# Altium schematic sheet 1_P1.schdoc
size 307 x 218 mm; Symbol: Drawing-Symbol_A4; Device: Drawing-Symbol_A4; @Project Name: elrsTransmitter; @Page Count: 1; @Update Date: 2026-03-08; @Create Date: 2026-03-08; @Schematic Name: Schematic2; @Page No: 1; @Page Name: P1; Company: EasyEDA.com; Version: V1.0; Page Size: A4; @Create Time: 09:29:20; @Update Time: 11:20:45; Width: 1170; Height: 825; Region Start: 1; X Region Count: 6; Y Region Count: 4; Blade Width: 10; Title Block Position: 3; @Board Name: PCB2
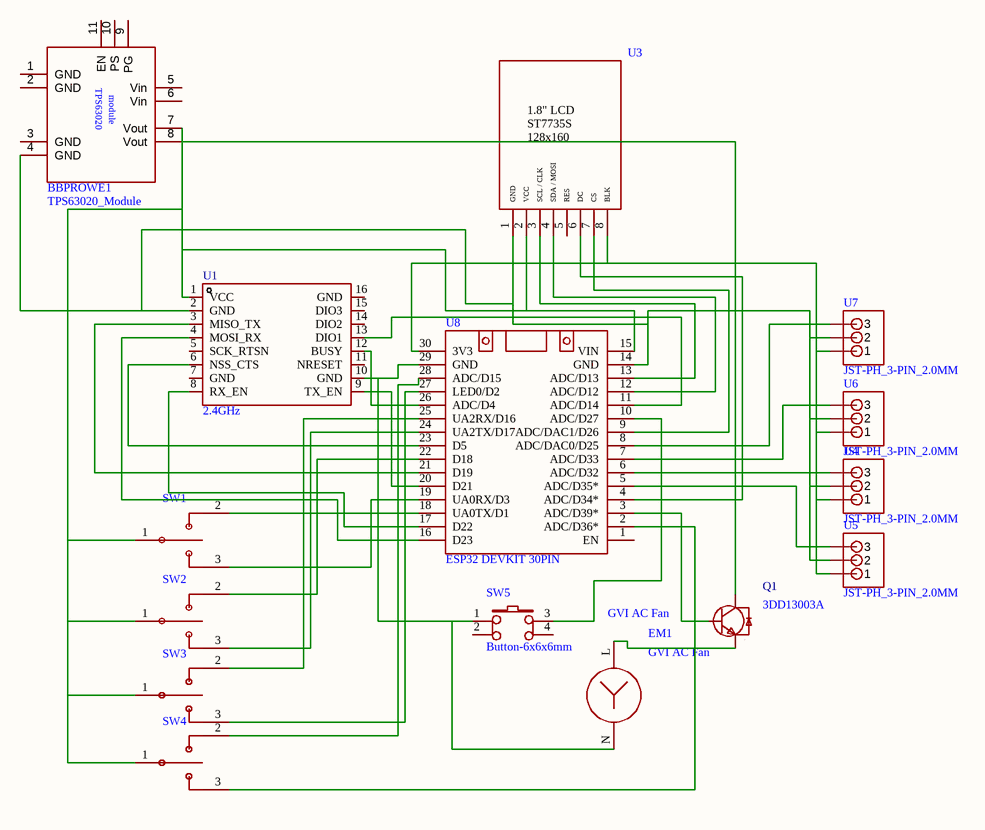
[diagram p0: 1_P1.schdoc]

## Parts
BBPROWE1  TPS63020_Module  [TPS63020_MODULE_PCB]
EM1  GVI AC Fan  [CONN-TH_2P-P2.54-V]
Q1  3DD13003A  [TO-92-3_L4.8-W3.7-P1.27-L]
SW1  (no value)  [3_Pin_Toggle_Switch_Footprint]
SW2  (no value)  [3_Pin_Toggle_Switch_Footprint]
SW3  (no value)  [3_Pin_Toggle_Switch_Footprint]
SW4  (no value)  [3_Pin_Toggle_Switch_Footprint]
SW5  Button-6x6x6mm  [SW-TH_4PIN-L6.00-W6.00]
U1  2.4GHz  [WIRELM-SMD_E28-2G4M27SX]
U3  (no value)  [WeAct 1.8 inch TFT ST7735S]
U4  JST-PH_3-PIN_2.0MM  [JST PH 3-PIN 2.0MM TOP ENTRY]
U5  JST-PH_3-PIN_2.0MM  [JST PH 3-PIN 2.0MM TOP ENTRY]
U6  JST-PH_3-PIN_2.0MM  [JST PH 3-PIN 2.0MM TOP ENTRY]
U7  JST-PH_3-PIN_2.0MM  [JST PH 3-PIN 2.0MM TOP ENTRY]
U8  ESP32 DEVKIT 30PIN  [ESP32 DEVKIT 30P]

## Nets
NetBBPROWE1_4: BBPROWE1.4(GND) U1.2(GND) U3.1(GND) U4.2 U5.2 U6.2 U7.2 U8.14(GND)
NetBBPROWE1_7: BBPROWE1.7(Vout) BBPROWE1.8(Vout) Q1.2(C) SW1.1 SW2.1 SW3.1 SW4.1 U1.1(VCC) U3.2(VCC) U8.15(VIN)
NetEM1_L: EM1.L Q1.1(E)
NetEM1_N: EM1.N SW5.1 U1.10(GND) U8.29(GND)
NetQ1_3: Q1.3(B) U8.3(ADC/D39*)
NetSW1_2: SW1.2 U8.18(UA0TX/D1)
NetSW1_3: SW1.3 U8.19(UA0RX/D3)
NetSW2_2: SW2.2 U8.22(D18)
NetSW2_3: SW2.3 U8.24(UA2TX/D17)
NetSW3_2: SW3.2 U8.25(UA2RX/D16)
NetSW3_3: SW3.3 U8.27(LED0/D2)
NetSW4_2: SW4.2 U8.28(ADC/D15)
NetSW4_3: SW4.3 U8.2(ADC/D36*)
NetSW5_3: SW5.3 U8.10(ADC/D27)
NetU1_3: U1.3(MISO_TX) U8.21(D19)
NetU1_4: U1.4(MOSI_RX) U8.16(D23)
NetU1_6: U1.6(NSS_CTS) U8.23(D5)
NetU1_8: U1.8(RX_EN) U8.17(D22)
NetU1_9: U1.9(TX_EN) U8.20(D21)
NetU1_12: U1.12(BUSY) U8.26(ADC/D4)
NetU1_13: U1.13(DIO1) U8.11(ADC/D14)
NetU3_3: U3.3(SCL_/_CLK) U8.13(ADC/D13)
NetU3_4: U3.4(SDA_/_MOSI) U8.12(ADC/D12)
NetU3_6: U3.6(DC) U8.4(ADC/D34*)
NetU3_7: U3.7(CS) U8.9(ADC/DAC1/D26)
NetU3_8: U3.8(BLK) U4.1 U5.1 U6.1 U7.1 U8.30(3V3)
NetU4_3: U4.3 U8.6(ADC/D32)
NetU5_3: U5.3 U8.5(ADC/D35*)
NetU6_3: U6.3 U8.7(ADC/D33)
NetU7_3: U7.3 U8.8(ADC/DAC0/D25)

Not connected (* = marked no-connect by the designer): BBPROWE1 1(GND) 2(GND) 3(GND) 5(Vin) 6(Vin) 9(PG) 10(PS) 11(EN); SW5 2 4; U1 5(SCK_RTSN) 7(GND) 11(NRESET) 14(DIO2) 15(DIO3) 16(GND); U3 5(RES); U8 1(EN)

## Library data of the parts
BBPROWE1 = TPS63020_Module: Add into BOM: yes
EM1 = GVI AC Fan: Add into BOM: yes
Q1 = 3DD13003A: Manufacturer: 吉林华微; Add into BOM: yes; Current - Collector(Ic): 1.5A; Collector - Emitter Voltage VCEO: 450V; Pd - Power Dissipation: 40W; Transition frequency(fT): 4MHz; Current - Collector Cutoff: 100uA; Vce Saturation(VCE(sat)): 2V@1.5A,0.5A
SW1-SW4 = 3_Position_Toggle_Switch: Add into BOM: yes
SW5 = Button-6x6x6mm: Manufacturer: BBJ; Manufacturer Part: Switch,6*6*6Plastic head,260G, 0.25mm,Straight line; Convert to PCB: yes
U1 = E28-2G4M27SX: Manufacturer: EBYTE(亿佰特); Add into BOM: yes
U3 = WeAct 1.8inch TFT Display ST7735: Symbol: IPS_LCD_1.8_ST7735S_128x160; Add into BOM: yes
U4-U7 = JST-PH_3-PIN_2.0MM: Add into BOM: yes
U8 = ESP32 DEVKIT 30PIN: Add into BOM: yes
